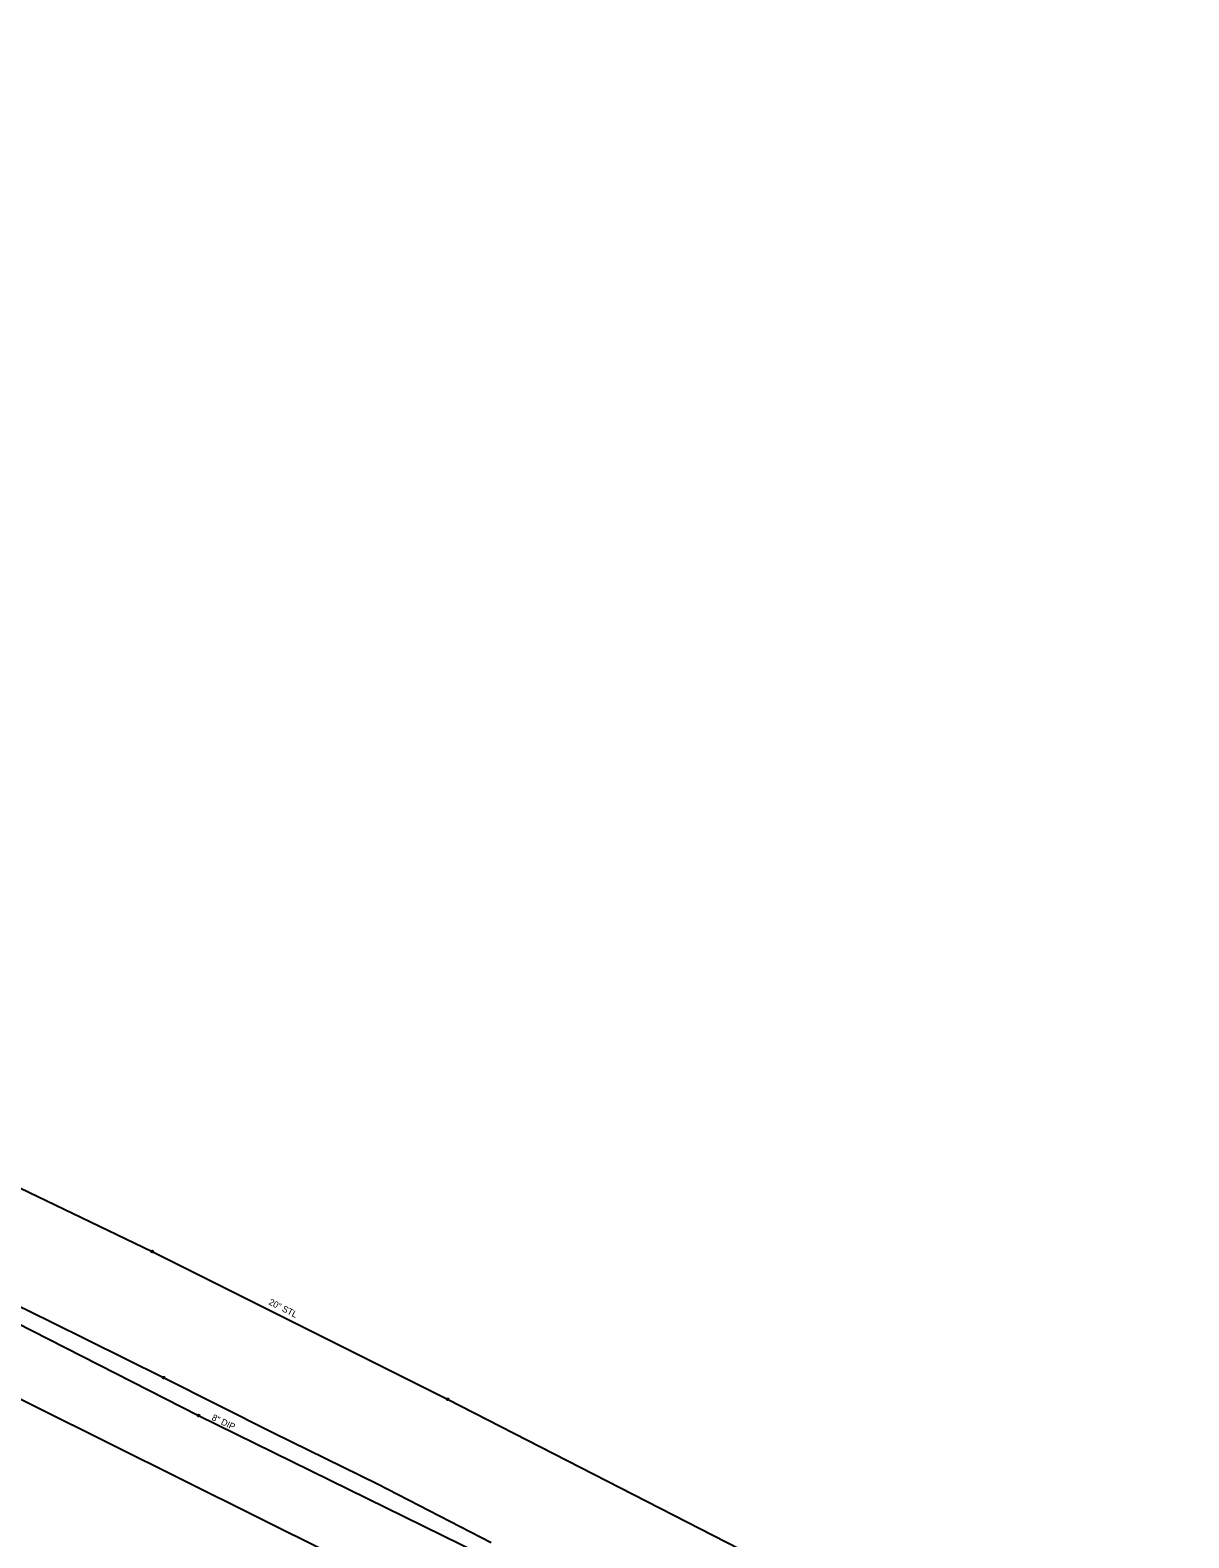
# Model space of a CAD drawing. Extents: x 2244485 to 2250986, y 199568 to 203007.
# Drawn here: x 2245934 to 2246567, y 202136 to 202958 of the extents above; entities that cross this region are included whole.
import ezdxf

# ---------------------------------------------------------------- set-up
doc = ezdxf.new("R2010")
doc.units = 0
for name, color, linetype in [('Default', 7, 'Continuous'), ('Exist Utilities Gas UG Line SUE LOS B', 7, 'Continuous'), ('Exist Utilities Gas UG Line SUE LOS B Text', 7, 'Continuous'), ('Exist Utilities Sanitary Sewer Forced Main SUE LOS B', 7, 'Continuous'), ('Exist Utilities Sanitary Sewer Forced Main SUE LOS B Text', 7, 'Continuous'), ('Exist Utilities Telephone UG Cable SUE LOS C', 7, 'Continuous'), ('Exist Utilities Telephone UG FO SUE LOS B', 7, 'Continuous')]:
    doc.layers.add(name, color=color, linetype=linetype)

# ---------------------------------------------------------------- blocks, each defined once
blk = doc.blocks.new('SurveyPointCell')
at = {"layer": 'Default'}
for p, q in [((-0.5, 0), (0.5, 0)), ((0, -0.5), (0, 0.5))]:
    blk.add_line(p, q, dxfattribs=at)
blk.add_circle((0, 0), 0.5, dxfattribs=at)

msp = doc.modelspace()

# ---------------------------------------------------------------- linework, layer by layer
at = {"layer": 'Exist Utilities Gas UG Line SUE LOS B'}
msp.add_lwpolyline([(2244658.96, 202958.49), (2244721.96, 202928.3), (2244863.47, 202856.19), (2244912.51, 202831.57), (2245070.07, 202752.33), (2245256.14, 202659.91), (2245331.4, 202622.29), (2245514.38, 202531.76), (2245606.53, 202488.05), (2245652.12, 202465.42), (2245827.69, 202375.08), (2246001.01, 202291.84), (2246162.3, 202211.17), (2246329.12, 202125.74), (2246513.99, 202036.93), (2246642.7, 201974.75), (2246734.96, 201930.33), (2246858.92, 201868.26), (2246999.42, 201799.12), (2247177.53, 201710.71), (2247331.7, 201633.3), (2247466.92, 201567.22), (2247602.4, 201501.88), (2247749.1, 201426.01)], dxfattribs=at)
at = {"layer": 'Exist Utilities Sanitary Sewer Forced Main SUE LOS B'}
msp.add_lwpolyline([(2245613.42, 202432.81), (2245612.33, 202430.62), (2245623.54, 202401.29), (2245742.14, 202343.1), (2245917.37, 202257.79), (2246026.41, 202202.34), (2246210.46, 202111.93), (2246345.24, 202046.28), (2246501.59, 201967.74), (2246585.87, 201926.12), (2246766.44, 201836.2), (2246874.3, 201784.12), (2246993.56, 201724.08), (2247186.6, 201626.85), (2247291.7, 201574.36), (2247419.93, 201509.91), (2247528.38, 201455.85), (2247631.36, 201405.97), (2247735.41, 201350.67), (2247801.59, 201317.51)], dxfattribs=at)
at = {"layer": 'Exist Utilities Telephone UG Cable SUE LOS C'}
msp.add_lwpolyline([(2245130.24, 202608.24), (2245342.53, 202504.23), (2245365.2, 202493.05), (2245368.49, 202493.82), (2245371.26, 202498.68), (2245389.55, 202529.63), (2245373.43, 202494.83), (2245372.62, 202491.73), (2245374.18, 202489.1), (2245390.76, 202481.45), (2245604.3, 202371.42), (2245815.4, 202267.89), (2246098.91, 202126.77), (2246431.3, 201961.17), (2246435.26, 201960.69), (2246439.92, 201963.48), (2246448.75, 201975.62), (2246463.67, 201997.05), (2246446.22, 201961.62), (2246445.59, 201956.98), (2246446.26, 201954.54), (2246473.42, 201940.75), (2246700.68, 201828.04)], dxfattribs=at)
at = {"layer": 'Exist Utilities Telephone UG FO SUE LOS B'}
msp.add_lwpolyline([(2245260.01, 202583.68), (2245475.72, 202477.57), (2245539.46, 202446.04), (2245564.49, 202433.2), (2245575.96, 202427.09), (2245584.49, 202422.12), (2245613.86, 202408.13), (2245635.9, 202399.1), (2245651.03, 202391.62), (2245656.6, 202391.2), (2245663.92, 202392.06), (2245682.86, 202383.66), (2245825.7, 202313.24), (2245887.18, 202282.16), (2245945.52, 202253.66), (2246007.29, 202222.98), (2246067.19, 202192.91), (2246123.94, 202164.93), (2246186.06, 202132.91)], dxfattribs=at)

# ---------------------------------------------------------------- block references
at = {"layer": 'Default'}
for p in [(2246001.01, 202291.84), (2246007.29, 202222.98), (2246162.3, 202211.17), (2246026.41, 202202.34)]:
    msp.add_blockref('SurveyPointCell', p, dxfattribs=at)

# ---------------------------------------------------------------- texts
at = {"layer": 'Exist Utilities Gas UG Line SUE LOS B Text'}
msp.add_text('20" STL', height=3.5, rotation=333.09153, dxfattribs=at).set_placement((2246064.29, 202263.11))
at = {"layer": 'Exist Utilities Sanitary Sewer Forced Main SUE LOS B Text'}
msp.add_text('8" DIP', height=3.5, rotation=334.4319, dxfattribs=at).set_placement((2246033.23, 202200.02))

doc.saveas('drawing.dxf')
